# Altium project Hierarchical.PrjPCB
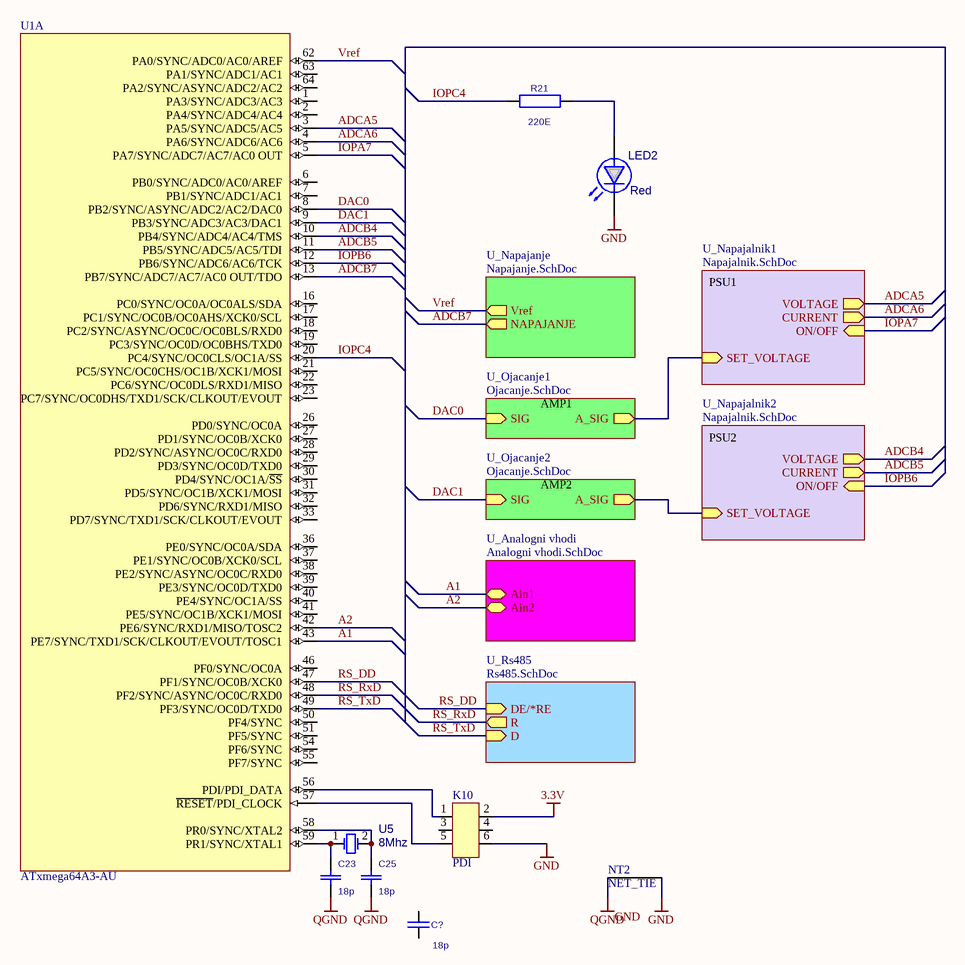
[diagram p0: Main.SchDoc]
6 sheets, 88 parts. Net scope: hierarchical (ports join the sheet entries above them; power ports are global).
Board file: Multichannel.PcbDoc
Sheets:
  Main.SchDoc
    U_Napajanje = Napajanje.SchDoc
    U_Rs485 = Rs485.SchDoc
    U_Ojacanje1 = Ojacanje.SchDoc
    U_Analogni vhodi = Analogni vhodi.SchDoc
    U_Napajalnik1 = Napajalnik.SchDoc
    U_Napajalnik2 = Napajalnik.SchDoc
    U_Ojacanje2 = Ojacanje.SchDoc

## Sheet Main.SchDoc
size A4

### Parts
C23  18p  [C0805]
C25  18p  [C0805]
C?  18p  [C0805]
K10  H2x3  [H2x3]  (value not drawn)
LED2  value Red  [LED0805]  (hidden comment: LED0805)
NT2  NET_TIE  [NET_TIE_LINE]  (net tie, no BOM)
R21  220E  [R0805]
U1  ATxmega64A3-AU  [64A_M]  (part A of 2)
U5  8Mhz  [HC49/4H_SMX]

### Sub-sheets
U_Analogni vhodi = Analogni vhodi.SchDoc: Ain1 (bidir), Ain2 (bidir)
U_Napajalnik1 = Napajalnik.SchDoc: VOLTAGE (out), CURRENT (out), ON/OFF (in), SET_VOLTAGE (in)
U_Napajalnik2 = Napajalnik.SchDoc: VOLTAGE (out), CURRENT (out), ON/OFF (in), SET_VOLTAGE (in)
U_Napajanje = Napajanje.SchDoc: NAPAJANJE (out), Vref (out)
U_Ojacanje1 = Ojacanje.SchDoc: SIG (in), A_SIG (out)
U_Ojacanje2 = Ojacanje.SchDoc: SIG (in), A_SIG (out)
U_Rs485 = Rs485.SchDoc: R (out), D (in), DE/*RE (in)

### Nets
3.3V: K10.2
GND: K10.6 LED2.K NT2.2
QGND: C23.1 C25.2 NT2.1
A1: U1.43(PE7/SYNC/TXD1/SCK/CLKOUT/EVOUT/TOSC1) ; sheet U_Analogni vhodi/Ain1
A2: U1.42(PE6/SYNC/RXD1/MISO/TOSC2) ; sheet U_Analogni vhodi/Ain2
ADCA5: U1.3(PA5/SYNC/ADC5/AC5) ; sheet U_Napajalnik1/VOLTAGE
ADCA6: U1.4(PA6/SYNC/ADC6/AC6) ; sheet U_Napajalnik1/CURRENT
ADCB4: U1.10(PB4/SYNC/ADC4/AC4/TMS) ; sheet U_Napajalnik2/VOLTAGE
ADCB5: U1.11(PB5/SYNC/ADC5/AC5/TDI) ; sheet U_Napajalnik2/CURRENT
ADCB7: U1.13(PB7/SYNC/ADC7/AC7/AC0_OUT/TDO) ; sheet U_Napajanje/NAPAJANJE
DAC0: U1.8(PB2/SYNC/ASYNC/ADC2/AC2/DAC0) ; sheet U_Ojacanje1/SIG
DAC1: U1.9(PB3/SYNC/ADC3/AC3/DAC1) ; sheet U_Ojacanje2/SIG
IOPA7: U1.5(PA7/SYNC/ADC7/AC7/AC0_OUT) ; sheet U_Napajalnik1/ON/OFF
IOPB6: U1.12(PB6/SYNC/ADC6/AC6/TCK) ; sheet U_Napajalnik2/ON/OFF
IOPC4: R21.1 U1.20(PC4/SYNC/OC0CLS/OC1A/SS)
RS_DD: U1.47(PF1/SYNC/OC0B/XCK0) ; sheet U_Rs485/DE/*RE
RS_RxD: U1.48(PF2/SYNC/ASYNC/OC0C/RXD0) ; sheet U_Rs485/R
RS_TxD: U1.49(PF3/SYNC/OC0D/TXD0) ; sheet U_Rs485/D
Vref: U1.62(PA0/SYNC/ADC0/AC0/AREF) ; sheet U_Napajanje/Vref
NetC23_2: C23.2 U1.59(PR1/SYNC/XTAL1) U5.1(OSC1)
NetC25_1: C25.1 U1.58(PR0/SYNC/XTAL2) U5.2(OSC2)
NetK4A_3: sheet U_Ojacanje1/A_SIG, sheet U_Napajalnik1/SET_VOLTAGE
NetK4B_3: sheet U_Napajalnik2/SET_VOLTAGE, sheet U_Ojacanje2/A_SIG
NetK10_1: K10.1 U1.56(PDI/PDI_DATA)
NetK10_5: K10.5 U1.57(~{RESET}/PDI_CLOCK)
NetLED2_A: LED2.A R21.2

Not connected (* = marked no-connect by the designer): C? 1 2; K10 3 4; U1 1(PA3/SYNC/ADC3/AC3) 2(PA4/SYNC/ADC4/AC4) 6(PB0/SYNC/ADC0/AC0/AREF) 7(PB1/SYNC/ADC1/AC1) 16(PC0/SYNC/OC0A/OC0ALS/SDA) 17(PC1/SYNC/OC0B/OC0AHS/XCK0/SCL) 18(PC2/SYNC/ASYNC/OC0C/OC0BLS/RXD0) 19(PC3/SYNC/OC0D/OC0BHS/TXD0) 21(PC5/SYNC/OC0CHS/OC1B/XCK1/MOSI) 22(PC6/SYNC/OC0DLS/RXD1/MISO) 23(PC7/SYNC/OC0DHS/TXD1/SCK/CLKOUT/EVOUT) 26(PD0/SYNC/OC0A) 27(PD1/SYNC/OC0B/XCK0) 28(PD2/SYNC/ASYNC/OC0C/RXD0) 29(PD3/SYNC/OC0D/TXD0) 30(PD4/SYNC/OC1A/~{SS}) 31(PD5/SYNC/OC1B/XCK1/MOSI) 32(PD6/SYNC/RXD1/MISO) 33(PD7/SYNC/TXD1/SCK/CLKOUT/EVOUT) 36(PE0/SYNC/OC0A/SDA) 37(PE1/SYNC/OC0B/XCK0/SCL) 38(PE2/SYNC/ASYNC/OC0C/RXD0) 39(PE3/SYNC/OC0D/TXD0) 40(PE4/SYNC/OC1A/SS) 41(PE5/SYNC/OC1B/XCK1/MOSI) 46(PF0/SYNC/OC0A) 50(PF4/SYNC) 51(PF5/SYNC) 54(PF6/SYNC) 55(PF7/SYNC) 63(PA1/SYNC/ADC1/AC1) 64(PA2/SYNC/ASYNC/ADC2/AC2)

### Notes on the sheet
- PSU1
- AMP1
- PSU2
- AMP2
- (near K10) PDI
- Labels drawn without touching a wire or pin: GND

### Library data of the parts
C23 C25 = SMD CAPACITOR: SMD Chip Capacitor; Tolerance: {Tolerance}
C? = C: Capacitor
K10 = H2x3: Header 2x3 (male)
LED2 = LED0805: Chip LED diode
R21 = SMD RESISTOR: Surface mount resistor; Power: {Power}
U1 = ATxmega64A3-AU: 8/16-bit AVR XMEGA A3 Microcontroller, 1.6-3.6V, 32MHz, 64KB + 4KB Flash, 2KB EEPROM, 4KB SRAM, 64-pin TQFP, Industrial Grade (-40°C to 85°C), Pb-Free
U5 = Q HC49 SMD: Q SMD; ComponentLink2DescA4: Datasheet; Note: PCB layout complies with manufacturer's recommendation.; ComponentLink1DescBC: Manufacturer Link

## Sheet Napajanje.SchDoc
size A4
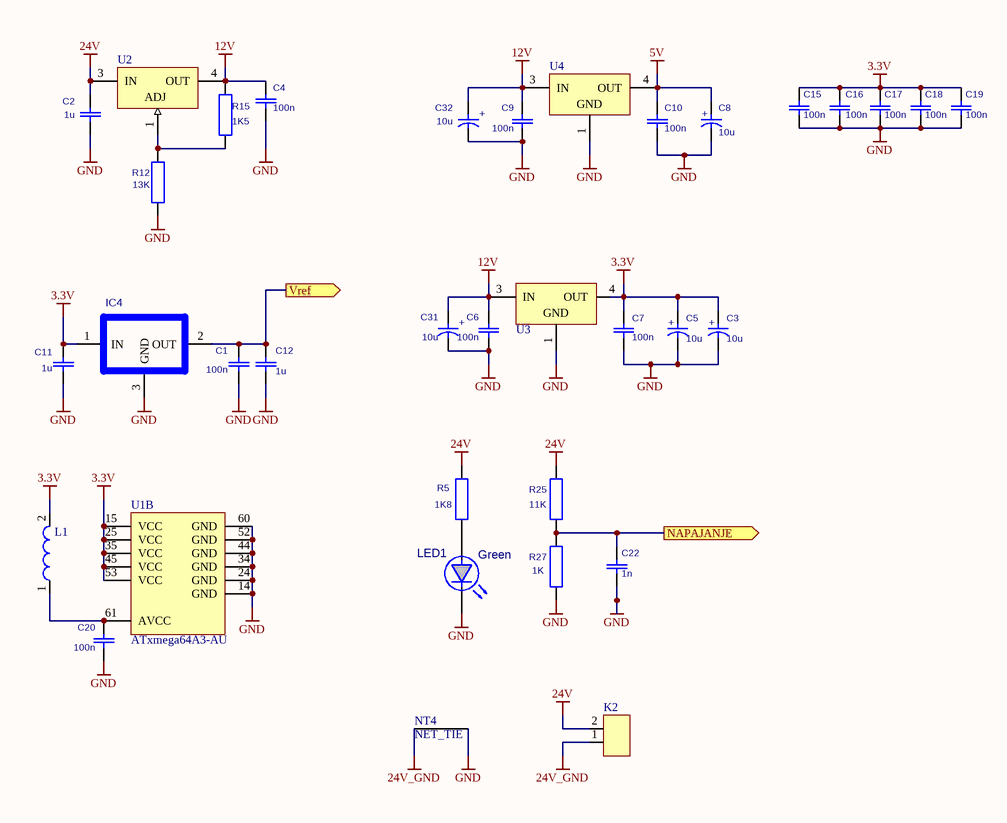
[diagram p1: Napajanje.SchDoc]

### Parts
C1  100n  [C0805]
C2  1u  [C0805]
C3  10u  [CT_A]
C4  100n  [C0805]
C5  10u  [CT_A]
C6  100n  [C0805]
C7  100n  [C0805]
C8  10u  [CT_A]
C9  100n  [C0805]
C10  100n  [C0805]
C11  1u  [C0805]
C12  1u  [C0805]
C15  100n  [C0805]
C16  100n  [C0805]
C17  100n  [C0805]
C18  100n  [C0805]
C19  100n  [C0805]
C20  100n  [C0805]
C22  1n  [C0805]
C31  10u  [CT_A]
C32  10u  [CT_A]
IC4  REF3025  [SOT23]  (value not drawn)
K2  CON_2pin_5mm  [CON_2pin_5mm]  (value not drawn)
L1  4279208  [SMD-0805]  (value not drawn)
LED1  value Green  [LED0805]  (hidden comment: LED0805)
NT4  NET_TIE  [NET_TIE_LINE]  (net tie, no BOM)
R5  1K8  [R0805]
R12  13K  [R0805]
R15  1K5  [R0805]
R25  11K  [R0805]
R27  1K  [R0805]
U1  ATxmega64A3-AU  [64A_N]  (part B of 2)
U2  LM317M  [TD03B_M]  (value not drawn)
U3  LM1117IDTX-3.3  [TD03B_M]  (value not drawn)
U4  LM1117IDTX-5.0  [TD03B_M]  (value not drawn)

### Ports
NAPAJANJE (out), Vref (out)

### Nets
3.3V: C3.1 C5.1 C7.1 C11.1 C15.1 C16.1 C17.1 C18.1 C19.1 IC4.1(IN) L1.2 U1.15(VCC) U1.25(VCC) U1.35(VCC) U1.45(VCC) U1.53(VCC) U3.4(OUT)
5V: C8.1 C10.1 U4.4(OUT)
12V: C4.1 C6.1 C9.1 C31.1 C32.1 R15.2 U2.4(OUT) U3.3(IN) U4.3(IN)
24V: C2.1 K2.2 R5.2 R25.1 U2.3(IN)
24V_GND: K2.1 NT4.1
GND: C1.2 C2.2 C3.2 C4.2 C5.2 C6.2 C7.2 C8.2 C9.2 C10.2 C11.2 C12.2 C15.2 C16.2 C17.2 C18.2 C19.2 C20.2 C22.2 C31.2 C32.2 IC4.3(GND) LED1.K NT4.2 R12.1 R27.2 U1.14(GND) U1.24(GND) U1.34(GND) U1.44(GND) U1.52(GND) U1.60(GND) U3.1(GND) U4.1(GND)
ADCB7: C22.1 R25.2 R27.1 ; port NAPAJANJE
Vref: C1.1 C12.1 IC4.2(OUT) ; port Vref
NetC20_1: C20.1 L1.1 U1.61(AVCC)
NetLED1_A: LED1.A R5.1
NetR12_2: R12.2 R15.1 U2.1(ADJ)

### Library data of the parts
C1 C2 C4 C6 C7 C9-C12 C15-C20 C22 = SMD CAPACITOR: as C23 on sheet Main
C3 C5 C8 C31 C32 = CT_A: {Description}; RefProducer: {RefProducer}; Geometry: {Geometry}; Tolerance: {Tolerance}; MinESR: {MinESR}; MaxESR: {MaxESR}; SolventProof: {SolventProof}; LifeTime: {LifeTime}; TempRange: {TempRange}; Reference: {Reference}; RefProducerCode: {RefProducerCode}; Z(-25deg)/Z(+20deg): {Z(-25deg)/Z(+20deg)}; MaxLeakageCurrent: {MaxLeakageCurrent}; MinRippleCurrent: {MinRippleCurrent}
IC4 = REF3040
K2 = CON_2pin_5mm: Konektor za  Bernic ohišja Serija 605, 5 mm raster
L1 = 74279208: SMD EMI Suppression Ferrite Bead WE-CBF, Z = 40 Ohm; Impedance: 40 Ohm
LED1 = LED0805: Chip LED diode
R5 R12 R15 R25 R27 = SMD RESISTOR: Surface mount resistor; Power: {Power}
U1 = ATxmega64A3-AU: as U1 on sheet Main
U2 = LM317MDT: 3-Terminal Adjustable Regulator, 3-pin TO-252; Manufacturer: National Semiconductor; PackageTopMarking: NSUZXYTT*LM317*MDT; PowerWise: N; CompType: LDO IC; High-Reliability: Y
U3 = LM1117IDTX-3.3: 800mA Low-Dropout Linear Regulator, 3-pin TO-252; Manufacturer: National Semiconductor; PackageTopMarking: NSUZXYTT*LM1117*IDT-3.3; PowerWise: N; CompType: LDO IC; High-Reliability: Y
U4 = LM1117IDTX-5.0: 800mA Low-Dropout Linear Regulator, 3-pin TO-252; Manufacturer: National Semiconductor; PackageTopMarking: NSUZXYTT*LM1117*IDT-5.0; PowerWise: N; CompType: LDO IC; High-Reliability: Y

## Sheet Rs485.SchDoc
size A4
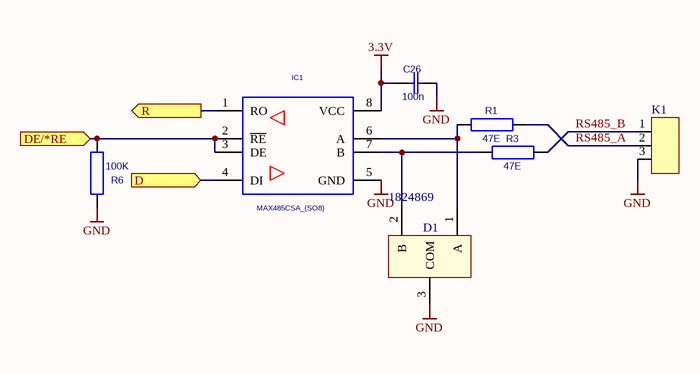
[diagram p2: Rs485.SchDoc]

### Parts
C26  100n  [C0805]
D1  Supplier Part Number 2: 1824869  [SOT23(BAT54)]  (hidden comment: CDSOT23-SM712)
IC1  MAX485CSA_(SO8)  [SO8R]
K1  CON_3pin_5mm  [COM_3pin_5mm]  (value not drawn)
R1  47E  [R0805]
R3  47E  [R0805]
R6  100K  [R0805]

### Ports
D (in), DE/*RE (in), R (out)

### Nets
3.3V: C26.1 IC1.8(VCC)
GND: C26.2 D1.3(COM) IC1.5(GND) K1.3 R6.1
RS485_A: K1.2 R1.2
RS485_B: K1.1 R3.2
RS_DD: IC1.2(~{RE}) IC1.3(DE) R6.2 ; port DE/*RE
RS_RxD: IC1.1(RO) ; port R
RS_TxD: IC1.4(DI) ; port D
NetD1_1: D1.1(A) IC1.6(A) R1.1
NetD1_2: D1.2(B) IC1.7(B) R3.1

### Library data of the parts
C26 = SMD CAPACITOR: as C23 on sheet Main
IC1 = MAX485CSA_(SO8): Line-Powered RS-232 Transceiver Chip; OriginalName: DS1275S; Value: {Value}; ComponentField6: Pin number 6 is Not Connected (NC); ComponentField7: Published 13-Oct-2000
K1 = CON_3pin_5mm: Konektor za Bernic ohišja, 5 mm
R1 R3 R6 = SMD RESISTOR: Surface mount resistor; Power: {Power}

## Sheet Ojacanje.SchDoc
size A4
Used 2 times, as channels U_Ojacanje1, U_Ojacanje2. Parts and nets are listed once, with the designators drawn on the sheet.
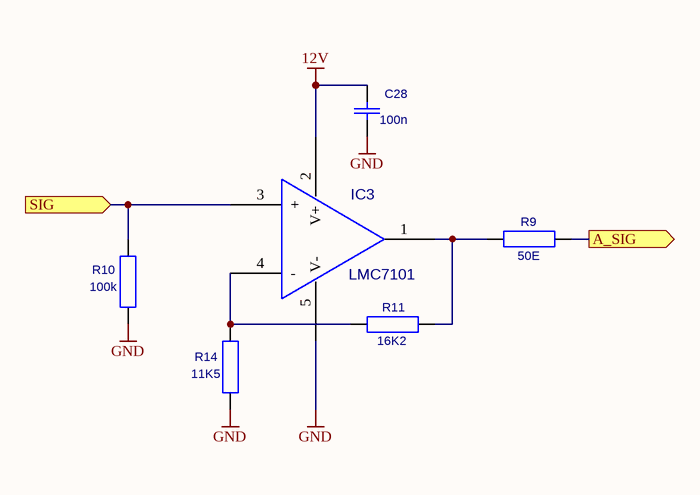
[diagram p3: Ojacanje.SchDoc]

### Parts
C28  100n  [C0805]
IC3  LMC7101  [SO-G5/P.95]
R9  50E  [R0805]
R10  100k  [R0805]
R11  16K2  [R0805]
R14  11K5  [R0805]

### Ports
A_SIG (out), SIG (in)

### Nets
12V: C28.1 IC3.2(V+)
GND: C28.2 IC3.5(V-) R10.1 R14.1
A_SIG: R9.2 ; port A_SIG
SIG: IC3.3(+) R10.2 ; port SIG
NetIC3_1: IC3.1 R9.1 R11.2
NetIC3_4: IC3.4(-) R11.1 R14.2

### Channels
U_Ojacanje1: designators end in A; ports A_SIG=NetK4A_3 SIG=DAC0
U_Ojacanje2: designators end in B; ports A_SIG=NetK4B_3 SIG=DAC1

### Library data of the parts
C28 = SMD CAPACITOR: as C23 on sheet Main
R9-R11 R14 = SMD RESISTOR: Surface mount resistor; Power: {Power}

## Sheet Analogni vhodi.SchDoc
size A4
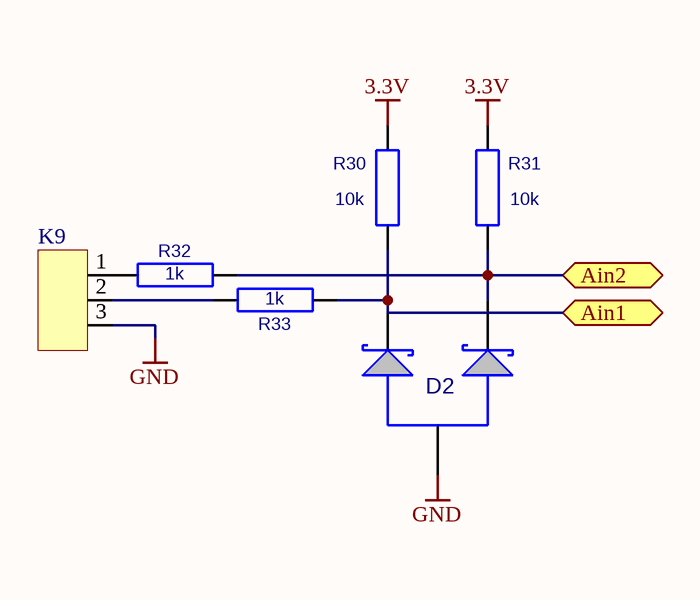
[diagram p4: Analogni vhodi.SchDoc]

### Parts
D2  BAT54A  [SOT23]  (value not drawn)
K9  CON_3pin_5mm  [COM_3pin_5mm]  (value not drawn)
R30  10k  [R0805]
R31  10k  [R0805]
R32  1k  [R0805]
R33  1k  [R0805]

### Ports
Ain1 (bidir), Ain2 (bidir)

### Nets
3.3V: R30.2 R31.2
GND: D2.2(A2) K9.3
A1: D2.3(K) R30.1 R33.1 ; port Ain1
A2: D2.1(A1) R31.1 R32.1 ; port Ain2
NetK9_1: K9.1 R32.2
NetK9_2: K9.2 R33.2

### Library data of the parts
D2 = BAT54A: ComponentLink2DescA4: Datasheet; Note: Pin 2 is not connected and is not drawn; ComponentLink1DescBC: Manufacturer Link
K9 = CON_3pin_5mm: Konektor za Bernic ohišja, 5 mm
R30-R33 = SMD RESISTOR: Surface mount resistor; Power: {Power}

## Sheet Napajalnik.SchDoc
size A4
Used 2 times, as channels U_Napajalnik1, U_Napajalnik2. Parts and nets are listed once, with the designators drawn on the sheet.
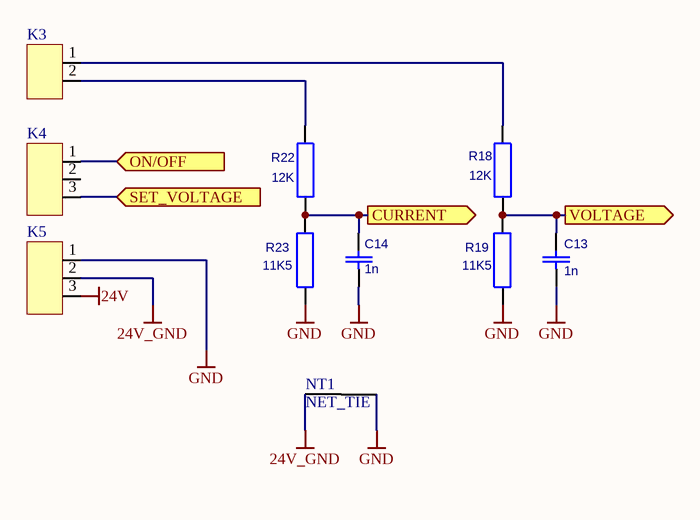
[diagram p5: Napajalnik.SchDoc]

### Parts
C13  1n  [C0805]
C14  1n  [C0805]
K3  CON_2pin_5mm  [CON_2pin_5mm]  (value not drawn)
K4  CON_3pin_5mm  [COM_3pin_5mm]  (value not drawn)
K5  CON_3pin_5mm  [COM_3pin_5mm]  (value not drawn)
NT1  NET_TIE  [NET_TIE_LINE]  (net tie, no BOM)
R18  12K  [R0805]
R19  11K5  [R0805]
R22  12K  [R0805]
R23  11K5  [R0805]

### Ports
CURRENT (out), ON/OFF (in), SET_VOLTAGE (in), VOLTAGE (out)

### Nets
24V: K5.3
24V_GND: K5.2 NT1.1
GND: C13.2 C14.2 K5.1 NT1.2 R19.2 R23.2
CURRENT: C14.1 R22.1 R23.1 ; port CURRENT
ON/OFF: K4.1 ; port ON/OFF
SET_VOLTAGE: K4.3 ; port SET_VOLTAGE
VOLTAGE: C13.1 R18.1 R19.1 ; port VOLTAGE
NetK3_1: K3.1 R18.2
NetK3_2: K3.2 R22.2

Not connected (* = marked no-connect by the designer): K4 2

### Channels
U_Napajalnik1: designators end in A; ports CURRENT=ADCA6 ON/OFF=IOPA7 SET_VOLTAGE=NetK4A_3 VOLTAGE=ADCA5
U_Napajalnik2: designators end in B; ports CURRENT=ADCB5 ON/OFF=IOPB6 SET_VOLTAGE=NetK4B_3 VOLTAGE=ADCB4

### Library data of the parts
C13 C14 = SMD CAPACITOR: as C23 on sheet Main
K3 = CON_2pin_5mm: as K2 on sheet Napajanje
K4 K5 = CON_3pin_5mm: Konektor za Bernic ohišja, 5 mm
R18 R19 R22 R23 = SMD RESISTOR: Surface mount resistor; Power: {Power}

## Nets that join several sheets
3.3V: Main (K10.2), Napajanje (17 pins), Rs485 (C26.1 IC1.8), Analogni vhodi (R30.2 R31.2)
12V: Napajanje (9 pins), U_Ojacanje1 (C28A.1 IC3A.2), U_Ojacanje2 (C28B.1 IC3B.2)
24V: Napajanje (5 pins), U_Napajalnik1 (K5A.3), U_Napajalnik2 (K5B.3)
24V_GND: Napajanje (K2.1 NT4.1), U_Napajalnik1 (K5A.2 NT1A.1), U_Napajalnik2 (K5B.2 NT1B.1)
GND: Main (K10.6 LED2.K NT2.2), Napajanje (34 pins), Rs485 (5 pins), U_Ojacanje1 (C28A.2 IC3A.5 R10A.1 R14A.1), Analogni vhodi (D2.2 K9.3), U_Napajalnik1 (6 pins), U_Napajalnik2 (6 pins), U_Ojacanje2 (C28B.2 IC3B.5 R10B.1 R14B.1)
A1: Main (U1.43), Analogni vhodi (D2.3 R30.1 R33.1)
A2: Main (U1.42), Analogni vhodi (D2.1 R31.1 R32.1)
ADCA5: Main (U1.3), U_Napajalnik1 (C13A.1 R18A.1 R19A.1)
ADCA6: Main (U1.4), U_Napajalnik1 (C14A.1 R22A.1 R23A.1)
ADCB4: Main (U1.10), U_Napajalnik2 (C13B.1 R18B.1 R19B.1)
ADCB5: Main (U1.11), U_Napajalnik2 (C14B.1 R22B.1 R23B.1)
ADCB7: Main (U1.13), Napajanje (C22.1 R25.2 R27.1)
DAC0: Main (U1.8), U_Ojacanje1 (IC3A.3 R10A.2)
DAC1: Main (U1.9), U_Ojacanje2 (IC3B.3 R10B.2)
IOPA7: Main (U1.5), U_Napajalnik1 (K4A.1)
IOPB6: Main (U1.12), U_Napajalnik2 (K4B.1)
NetK4A_3: U_Ojacanje1 (R9A.2), U_Napajalnik1 (K4A.3)
NetK4B_3: U_Napajalnik2 (K4B.3), U_Ojacanje2 (R9B.2)
RS_DD: Main (U1.47), Rs485 (IC1.2 IC1.3 R6.2)
RS_RxD: Main (U1.48), Rs485 (IC1.1)
RS_TxD: Main (U1.49), Rs485 (IC1.4)
Vref: Main (U1.62), Napajanje (C1.1 C12.1 IC4.2)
